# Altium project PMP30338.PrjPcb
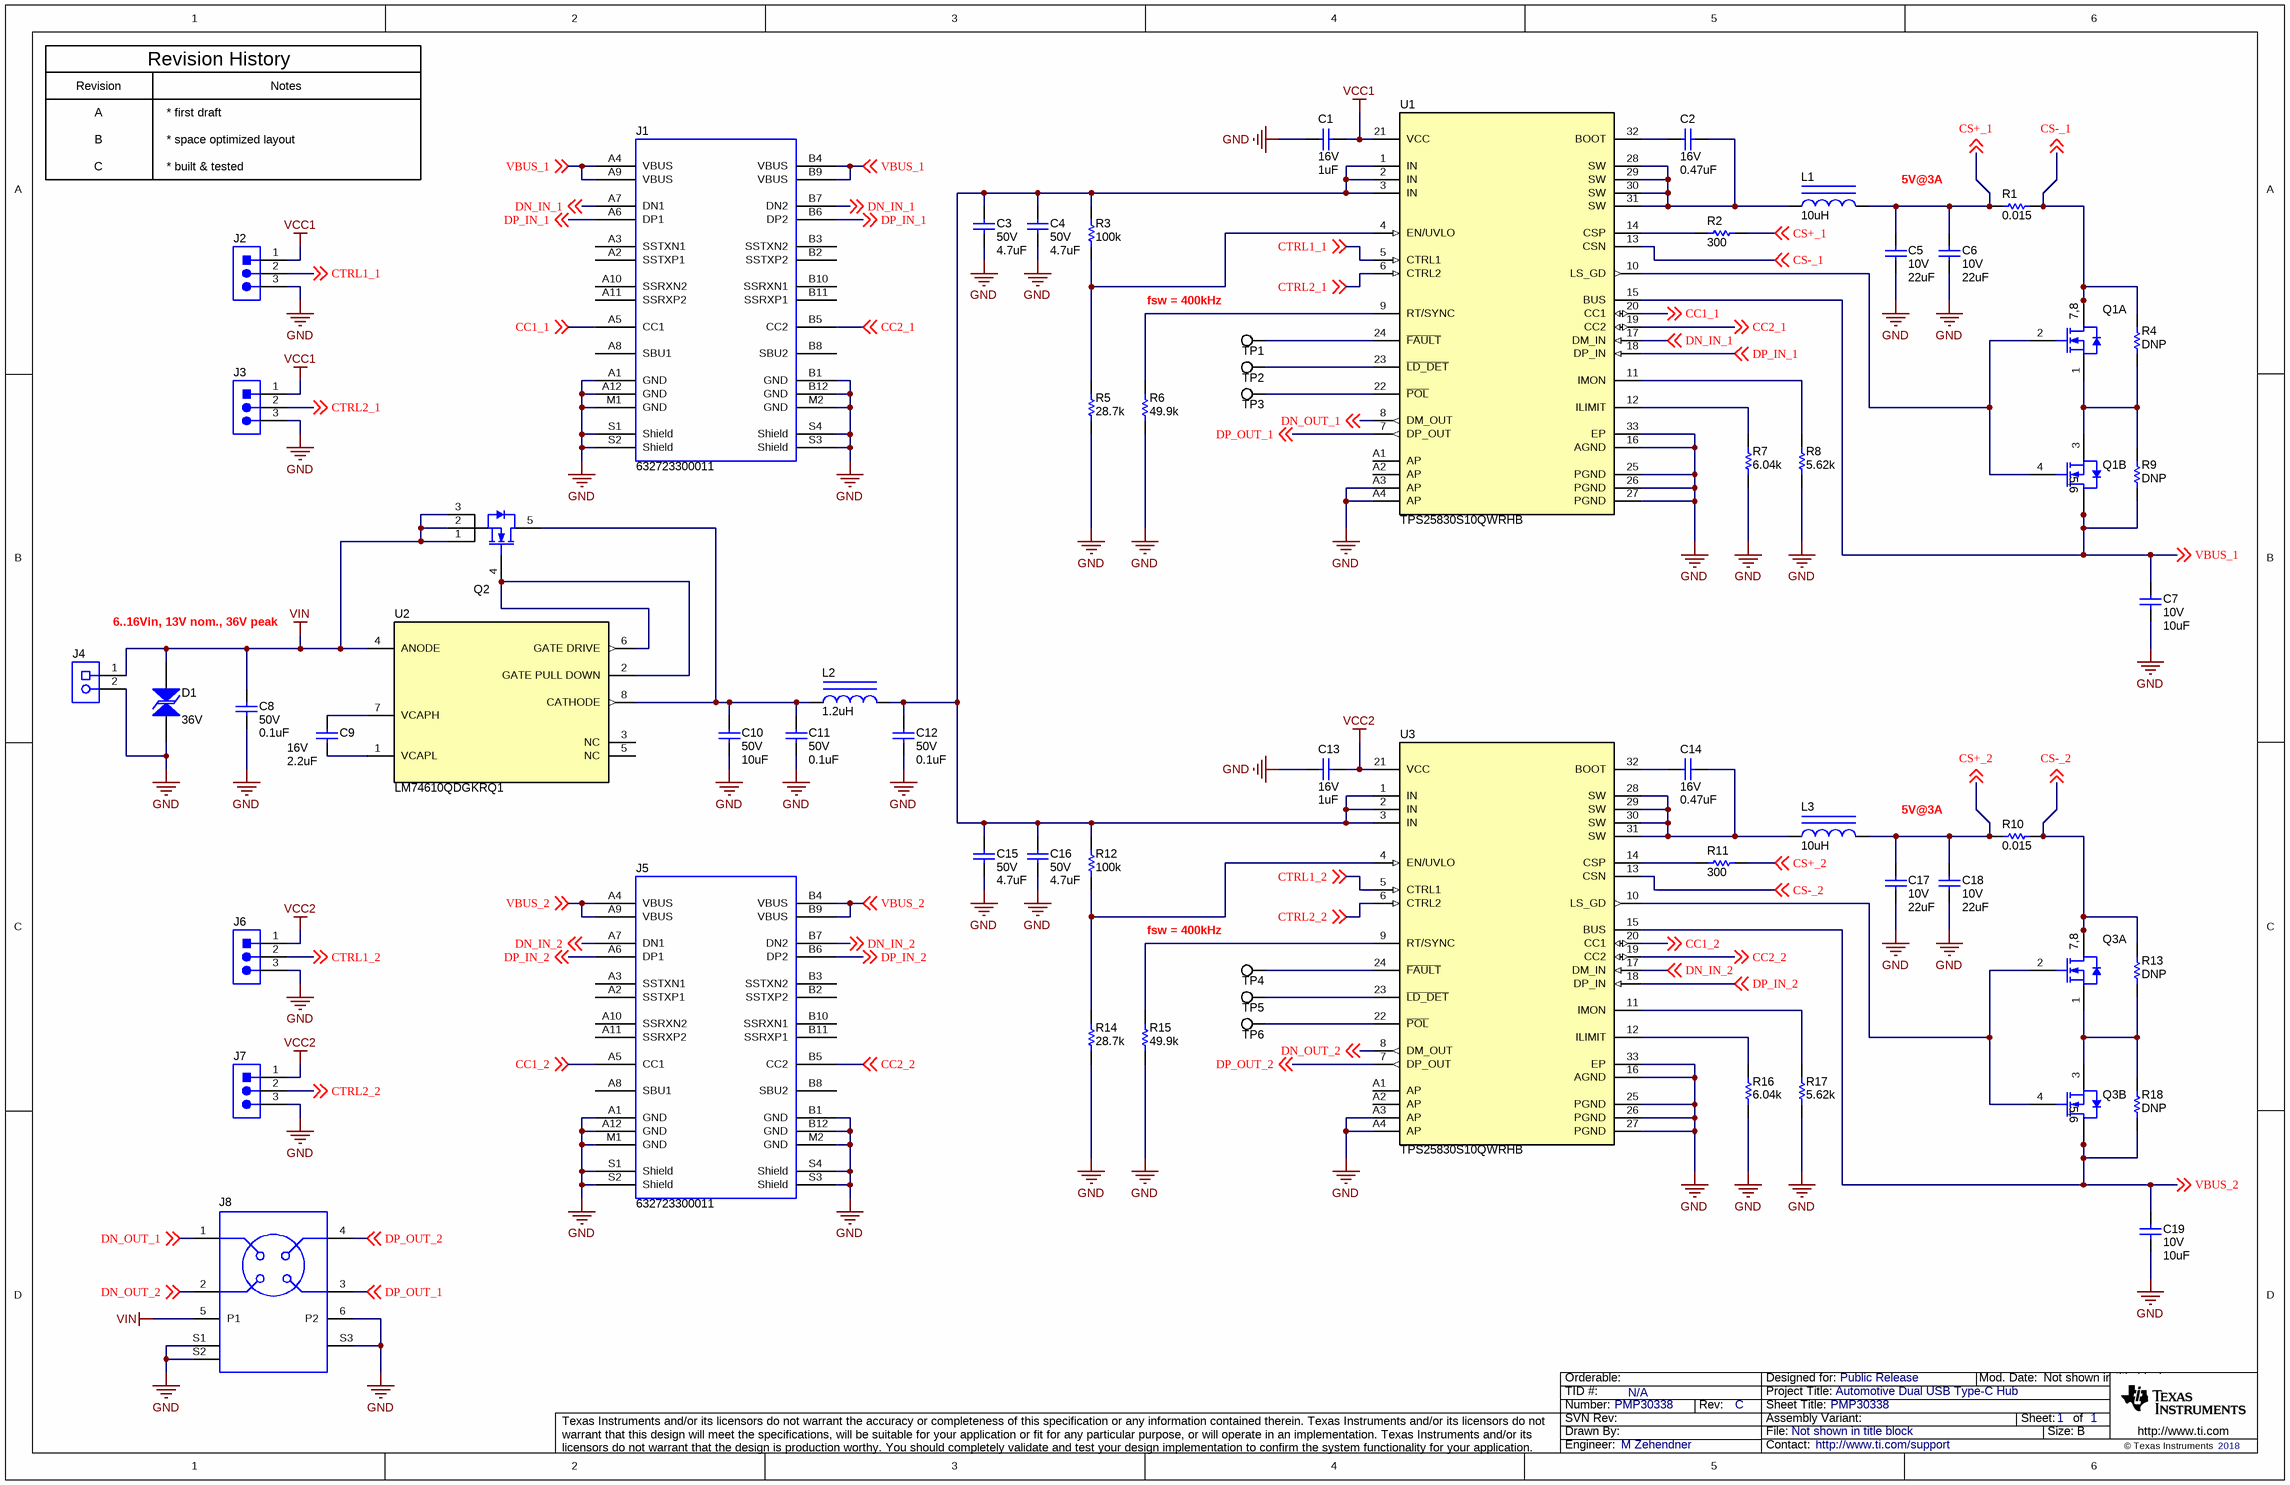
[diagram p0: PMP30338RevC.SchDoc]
TID: N/A; TechSupport: http://www.ti.com/support; SCH_Rev: C; PRJ_Title: Automotive Dual USB Type-C Hub; PRJ_Number: PMP30338; PRJ_Engineer: M Zehendner; PRJ_Customer: Public Release; PCB_Rev: B; PCB_Layout: Who did the Layout?; CopyrightYear: 2018
1 sheet, 61 parts. Net scope: global (net labels, ports and power ports of the same name join across sheets).
Board file: PMP30338.PcbDoc

## Sheet PMP30338RevC.SchDoc: PMP30338
size 431 x 279 mm; Date: Not shown in title block; ApprovedBy: Not shown in title block; CheckedBy: Not shown in title block; Author: Not shown in title block; CompanyName: Not shown in title block; Engineer: Not shown in title block; Organization: Not shown in title block; Address1: Not shown in title block; Address2: Not shown in title block; Address3: Not shown in title block; Address4: Not shown in title block; DocumentNumber: 1; Revision: Use project parameter SCH_Rev; SheetNumber: 1; SheetTotal: 1; PageSetup: Record=PageOptions¦CenterHorizontal=True¦CenterVertical=True¦PrintScale=1.00¦XCorrection=1.00¦YCorrection=1.00¦PrintKind=0¦BorderSize=5000000¦LeftOffset=0¦BottomOffset=0¦Orientation=2¦PaperLength=1000¦PaperWidth=1000¦Scale=100¦PaperSource=15¦PrintQuality=600¦MediaType=1¦DitherType=10¦PaperKind=Letter¦PrintScaleMode=1

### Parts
C1  VDC_V: 16V  ValueDisplayed: 1uF  [0805_HV]  (hidden comment: GRM21BR71C105MA01L)
C2  VDC_V: 16V  ValueDisplayed: 0.47uF  [0603]  (hidden comment: GRM188R71C474KA88D)
C3  VDC_V: 50V  ValueDisplayed: 4.7uF  [1206_180]  (hidden comment: GRM31CR71H475KA12L)
C4  VDC_V: 50V  ValueDisplayed: 4.7uF  [1206_180]  (hidden comment: GRM31CR71H475KA12L)
C5  VDC_V: 10V  ValueDisplayed: 22uF  [1210_270]  (hidden comment: GRM32ER71A226ME20L)
C6  VDC_V: 10V  ValueDisplayed: 22uF  [1210_270]  (hidden comment: GRM32ER71A226ME20L)
C7  VDC_V: 10V  ValueDisplayed: 10uF  [0805_HV]  (hidden comment: GRM21BR71A106ME51L)
C8  VDC_V: 50V  ValueDisplayed: 0.1uF  [0603]  (hidden comment: GRM188R71H104KA93D)
C9  VDC_V: 16V  ValueDisplayed: 2.2uF  [0805_HV]  (hidden comment: GRM219R71C225KE15)
C10  VDC_V: 50V  ValueDisplayed: 10uF  [1210_270]  (hidden comment: GRM32ER71H106MA12)
C11  VDC_V: 50V  ValueDisplayed: 0.1uF  [0603]  (hidden comment: GRM188R71H104KA93D)
C12  VDC_V: 50V  ValueDisplayed: 0.1uF  [0603]  (hidden comment: GRM188R71H104KA93D)
C13  VDC_V: 16V  ValueDisplayed: 1uF  [0805_HV]  (hidden comment: GRM21BR71C105MA01L)
C14  VDC_V: 16V  ValueDisplayed: 0.47uF  [0603]  (hidden comment: GRM188R71C474KA88D)
C15  VDC_V: 50V  ValueDisplayed: 4.7uF  [1206_180]  (hidden comment: GRM31CR71H475KA12L)
C16  VDC_V: 50V  ValueDisplayed: 4.7uF  [1206_180]  (hidden comment: GRM31CR71H475KA12L)
C17  VDC_V: 10V  ValueDisplayed: 22uF  [1210_270]  (hidden comment: GRM32ER71A226ME20L)
C18  VDC_V: 10V  ValueDisplayed: 22uF  [1210_270]  (hidden comment: GRM32ER71A226ME20L)
C19  VDC_V: 10V  ValueDisplayed: 10uF  [0805_HV]  (hidden comment: GRM21BR71A106ME51L)
D1  value 36V  [SMB-Bi]  (hidden comment: SM6T42CAY)
J1  632723300011  [Wurth_632_723_300_011]
J2  800-10-003-10-001000  [Mill-Max_800-10-003-10-001000]  (value not drawn)
J3  800-10-003-10-001000  [Mill-Max_800-10-003-10-001000]  (value not drawn)
J4  691 101 710 002  [Wurth_691101710002]  (value not drawn)
J5  632723300011  [Wurth_632_723_300_011]
J6  800-10-003-10-001000  [Mill-Max_800-10-003-10-001000]  (value not drawn)
J7  800-10-003-10-001000  [Mill-Max_800-10-003-10-001000]  (value not drawn)
J8  99S20D-40MA5-D  [Rosenberger_99S20D-40MA5-D]  (value not drawn)
L1  ValueDisplayed: 10uH  [XAL5050]  (hidden comment: XAL5050-103MEB)
L2  ValueDisplayed: 1.2uH  [XAL5030]  (hidden comment: XAL5030-122MEB)
L3  ValueDisplayed: 10uH  [XAL5050]  (hidden comment: XAL5050-103MEB)
Q1  BUK9K8R7-40E,115  [SOT1205]  (value not drawn)  (parts A,B of 2)
Q2  SQJ412EP-T1-GE3  [PowerPAK_SO-8L]  (value not drawn)
Q3  BUK9K8R7-40E,115  [SOT1205]  (value not drawn)  (parts A,B of 2)
R1  ValueDisplayed: 0.015  [1206]  (hidden comment: CSR1206FK15L0)
R2  ValueDisplayed: 300  [0603]  (hidden comment: CRCW0603300RJNEA)
R3  ValueDisplayed: 100k  [0603]  (hidden comment: CRCW0603100KFKEA)
R4  ValueDisplayed: DNP  [1206]  (hidden comment: RC1206JR-070RL)
R5  ValueDisplayed: 28.7k  [0603]  (hidden comment: CRCW060328K7FKEA)
R6  ValueDisplayed: 49.9k  [0603]  (hidden comment: CRCW060349K9FKEA)
R7  ValueDisplayed: 6.04k  [0603]  (hidden comment: CRCW06036K04FKEA)
R8  ValueDisplayed: 5.62k  [0603]  (hidden comment: CRCW06035K62FKEA)
R9  ValueDisplayed: DNP  [1206]  (hidden comment: RC1206JR-070RL)
R10  ValueDisplayed: 0.015  [1206]  (hidden comment: CSR1206FK15L0)
R11  ValueDisplayed: 300  [0603]  (hidden comment: CRCW0603300RJNEA)
R12  ValueDisplayed: 100k  [0603]  (hidden comment: CRCW0603100KFKEA)
R13  ValueDisplayed: DNP  [1206]  (hidden comment: RC1206JR-070RL)
R14  ValueDisplayed: 28.7k  [0603]  (hidden comment: CRCW060328K7FKEA)
R15  ValueDisplayed: 49.9k  [0603]  (hidden comment: CRCW060349K9FKEA)
R16  ValueDisplayed: 6.04k  [0603]  (hidden comment: CRCW06036K04FKEA)
R17  ValueDisplayed: 5.62k  [0603]  (hidden comment: CRCW06035K62FKEA)
R18  ValueDisplayed: DNP  [1206]  (hidden comment: RC1206JR-070RL)
TP1  5012  [Keystone5012]  (value not drawn)
TP2  5012  [Keystone5012]  (value not drawn)
TP3  5012  [Keystone5012]  (value not drawn)
TP4  5012  [Keystone5012]  (value not drawn)
TP5  5012  [Keystone5012]  (value not drawn)
TP6  5012  [Keystone5012]  (value not drawn)
U1  TPS25830S10QWRHB  [RHB0032R]
U2  LM74610QDGKRQ1  [DGK0008A_L]
U3  TPS25830S10QWRHB  [RHB0032R]

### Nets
GND: C1.2 C3.2 C4.2 C5.2 C6.2 C7.2 C8.2 C10.2 C11.2 C12.2 C13.2 C15.2 C16.2 C17.2 C18.2 C19.2 D1.1 J1.A1(GND) J1.A12(GND) J1.B1(GND) J1.B12(GND) J1.M1(GND) J1.M2(GND) J1.S1(Shield) J1.S2(Shield) J1.S3(Shield) J1.S4(Shield) J2.3 J3.3 J4.2 J5.A1(GND) J5.A12(GND) J5.B1(GND) J5.B12(GND) J5.M1(GND) J5.M2(GND) J5.S1(Shield) J5.S2(Shield) J5.S3(Shield) J5.S4(Shield) J6.3 J7.3 J8.6(P2) J8.S1 J8.S2 J8.S3 R5.1 R6.1 R7.1 R8.1 R14.1 R15.1 R16.1 R17.1 U1.16(AGND) U1.25(PGND) U1.26(PGND) U1.27(PGND) U1.33(EP) U1.A3(AP) U1.A4(AP) U3.16(AGND) U3.25(PGND) U3.26(PGND) U3.27(PGND) U3.33(EP) U3.A3(AP) U3.A4(AP)
VCC1: C1.1 J2.1 J3.1 U1.21(VCC)
VCC2: C13.1 J6.1 J7.1 U3.21(VCC)
VIN: C8.1 D1.2 J4.1 J8.5(P1) Q2.1(S) Q2.2(S) Q2.3(S) U2.4(ANODE)
CC1_1: J1.A5(CC1) U1.20(CC1) ; off-sheet CC1_1
CC1_2: J5.A5(CC1) U3.20(CC1) ; off-sheet CC1_2
CC2_1: J1.B5(CC2) U1.19(CC2) ; off-sheet CC2_1
CC2_2: J5.B5(CC2) U3.19(CC2) ; off-sheet CC2_2
CS+_1: C5.1 C6.1 L1.2 R1.1 R2.2 ; off-sheet CS+_1
CS+_2: C17.1 C18.1 L3.2 R10.1 R11.2 ; off-sheet CS+_2
CS-_1: Q1.7(D) Q1.8(D) R1.2 R4.2 U1.13(CSN) ; off-sheet CS-_1
CS-_2: Q3.7(D) Q3.8(D) R10.2 R13.2 U3.13(CSN) ; off-sheet CS-_2
CTRL1_1: J2.2 U1.5(CTRL1) ; off-sheet CTRL1_1
CTRL1_2: J6.2 U3.5(CTRL1) ; off-sheet CTRL1_2
CTRL2_1: J3.2 U1.6(CTRL2) ; off-sheet CTRL2_1
CTRL2_2: J7.2 U3.6(CTRL2) ; off-sheet CTRL2_2
DN_IN_1: J1.A7(DN1) J1.B7(DN2) U1.17(DM_IN) ; off-sheet DN_IN_1
DN_IN_2: J5.A7(DN1) J5.B7(DN2) U3.17(DM_IN) ; off-sheet DN_IN_2
DN_OUT_1: J8.1 U1.8(DM_OUT) ; off-sheet DN_OUT_1
DN_OUT_2: J8.2 U3.8(DM_OUT) ; off-sheet DN_OUT_2
DP_IN_1: J1.A6(DP1) J1.B6(DP2) U1.18(DP_IN) ; off-sheet DP_IN_1
DP_IN_2: J5.A6(DP1) J5.B6(DP2) U3.18(DP_IN) ; off-sheet DP_IN_2
DP_OUT_1: J8.3 U1.7(DP_OUT) ; off-sheet DP_OUT_1
DP_OUT_2: J8.4 U3.7(DP_OUT) ; off-sheet DP_OUT_2
VBUS_1: C7.1 J1.A4(VBUS) J1.A9(VBUS) J1.B4(VBUS) J1.B9(VBUS) Q1.5(D) Q1.6(D) R9.1 U1.15(BUS) ; off-sheet VBUS_1
VBUS_2: C19.1 J5.A4(VBUS) J5.A9(VBUS) J5.B4(VBUS) J5.B9(VBUS) Q3.5(D) Q3.6(D) R18.1 U3.15(BUS) ; off-sheet VBUS_2
NetC2_1: C2.1 L1.1 U1.28(SW) U1.29(SW) U1.30(SW) U1.31(SW)
NetC2_2: C2.2 U1.32(BOOT)
NetC3_1: C3.1 C4.1 C12.1 C15.1 C16.1 L2.2 R3.2 R12.2 U1.1(IN) U1.2(IN) U1.3(IN) U3.1(IN) U3.2(IN) U3.3(IN)
NetC9_1: C9.1 U2.7(VCAPH)
NetC9_2: C9.2 U2.1(VCAPL)
NetC10_1: C10.1 C11.1 L2.1 Q2.5(D) U2.8(CATHODE)
NetC14_1: C14.1 L3.1 U3.28(SW) U3.29(SW) U3.30(SW) U3.31(SW)
NetC14_2: C14.2 U3.32(BOOT)
NetQ1_1: Q1.1(S) Q1.3(S) R4.1 R9.2
NetQ1_2: Q1.2(G) Q1.4(G) U1.10(LS_GD)
NetQ2_4: Q2.4(G) U2.2(GATE_PULL_DOWN) U2.6(GATE_DRIVE)
NetQ3_1: Q3.1(S) Q3.3(S) R13.1 R18.2
NetQ3_2: Q3.2(G) Q3.4(G) U3.10(LS_GD)
NetR2_1: R2.1 U1.14(CSP)
NetR3_1: R3.1 R5.2 U1.4(EN/UVLO)
NetR6_2: R6.2 U1.9(RT/SYNC)
NetR7_2: R7.2 U1.12(ILIMIT)
NetR8_2: R8.2 U1.11(IMON)
NetR11_1: R11.1 U3.14(CSP)
NetR12_1: R12.1 R14.2 U3.4(EN/UVLO)
NetR15_2: R15.2 U3.9(RT/SYNC)
NetR16_2: R16.2 U3.12(ILIMIT)
NetR17_2: R17.2 U3.11(IMON)
NetTP1_1: TP1.1 U1.24(~{FAULT})
NetTP2_1: TP2.1 U1.23(~{LD_DET})
NetTP3_1: TP3.1 U1.22(~{POL})
NetTP4_1: TP4.1 U3.24(~{FAULT})
NetTP5_1: TP5.1 U3.23(~{LD_DET})
NetTP6_1: TP6.1 U3.22(~{POL})

Not connected (* = marked no-connect by the designer): J1 A2(SSTXP1) A3(SSTXN1) A8(SBU1) A10(SSRXN2) A11(SSRXP2) B2(SSTXP2) B3(SSTXN2) B8(SBU2) B10(SSRXN1) B11(SSRXP1); J5 A2(SSTXP1) A3(SSTXN1) A8(SBU1) A10(SSRXN2) A11(SSRXP2) B2(SSTXP2) B3(SSTXN2) B8(SBU2) B10(SSRXN1) B11(SSRXP1); U1 A1(AP) A2(AP); U2 3(NC) 5(NC); U3 A1(AP) A2(AP)

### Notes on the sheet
- Revision
- Revision History
- Notes
- A
- B
- C
- * first draft
- * space optimized layout
- * built & tested
- 5V@3A
- fsw = 400kHz
- 6..16Vin, 13V nom., 36V peak

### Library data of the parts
C1 C13 = CMP-0008324-2: CAP, CERM, 1 uF, 16 V, +/- 20%, X7R, 0805; Manufacturer: MuRata; TaMin_C: -55°C; ESR_ohm: 3m; Polarized: N; SizeAreaWB_mm2: 6.75; Value1: 0.003 ohm; U/M: EA; Value: 1uF; TaMax_C: 125°C; SizeZ_mm: 1.45; SizeX_mm: 2; SizeY_mm: 1.25; Cap_Case: 0805; SizeArea_mm2: 2.5; Cap_F: 1µF; AEC Category: Q200
C2 C14 = CMP-0007398-2: CAP, CERM, 0.47 uF, 16 V, +/- 10%, X7R, 0603; Manufacturer: MuRata; TaMin_C: -55°C; Polarized: N; SizeAreaWB_mm2: 4.68; Value1: Unknown; U/M: EA; Value: 0.47uF; TaMax_C: 125°C; SizeZ_mm: 1; SizeX_mm: 1.6; SizeY_mm: 0.8; SizeArea_mm2: 1.28; Cap_F: 470nF; AEC Category: Q200
C3 C4 C15 C16 = CMP-0008969-2: CAP, CERM, 4.7 uF, 50 V, +/- 10%, X7R, 1206; Manufacturer: MuRata; TaMin_C: -55°C; Polarized: N; SizeAreaWB_mm2: 10.92; Value1: Unknown; U/M: EA; Value: 4.7uF; TaMax_C: 125°C; SizeZ_mm: 1.8; SizeX_mm: 3.2; SizeY_mm: 1.6; Cap_Case: 2220; SizeArea_mm2: 5.12; Cap_F: 4.7µF; AEC Category: Q200
C5 C6 C17 C18 = CMP-0009219-2: CAP, CERM, 22 uF, 10 V, +/- 10%, X7R, 1210; Manufacturer: MuRata; TaMin_C: -55°C; ESR_ohm: 2m; Polarized: N; SizeAreaWB_mm2: 14.7; Value1: 0.002 ohm; U/M: EA; Value: 22uF; TaMax_C: 125°C; SizeZ_mm: 2.7; SizeX_mm: 3.2; SizeY_mm: 2.5; Cap_Case: 1210; SizeArea_mm2: 8; Cap_F: 22µF; IRMS_A: 3.2A; AEC Category: Q200
C7 C19 = CMP-0008316-2: CAP, CERM, 10 uF, 10 V, +/- 20%, X7R, 0805; Manufacturer: MuRata; TaMin_C: -55°C; Polarized: N; SizeAreaWB_mm2: 6.75; Value1: Unknown; U/M: EA; Value: 10uF; TaMax_C: 125°C; SizeZ_mm: 1.45; SizeX_mm: 2; SizeY_mm: 1.25; Cap_Case: 0805; SizeArea_mm2: 2.5; Cap_F: 10µF; AEC Category: Q200
C8 C11 C12 = CMP-0007434-2: CAP, CERM, 0.1 uF, 50 V, +/- 10%, X7R, 0603; Manufacturer: MuRata; TaMin_C: -55°C; Polarized: N; SizeAreaWB_mm2: 4.68; Value1: Unknown; U/M: EA; Value: 0.1uF; TaMax_C: 125°C; SizeZ_mm: 1; SizeX_mm: 1.6; SizeY_mm: 0.8; SizeArea_mm2: 1.28; Cap_F: 100nF; AEC Category: Q200
C9 = CMP-0008211-2: CAP, CERM, 2.2 uF, 16 V, +/- 10%, X7R, 0805; Manufacturer: MuRata; TaMin_C: -55°C; Polarized: N; SizeAreaWB_mm2: 6.75; Value1: Unknown; U/M: EA; Value: 2.2uF; TaMax_C: 125°C; SizeZ_mm: 1.45; SizeX_mm: 2; SizeY_mm: 1.25; Cap_Case: 0805; SizeArea_mm2: 2.5; Cap_F: 2.2µF; AEC Category: Q200
C10 = CMP-0009227-2: CAP, CERM, 10 uF, 50 V, +/- 20%, X7R, 1210; Manufacturer: MuRata; TaMin_C: -55°C; Polarized: N; SizeAreaWB_mm2: 14.7; Value1: Unknown; U/M: EA; Value: 10uF; TaMax_C: 125°C; SizeZ_mm: 2.7; SizeX_mm: 3.2; SizeY_mm: 2.5; Cap_Case: 1210; SizeArea_mm2: 8; Cap_F: 10µF; AEC Category: Q200
D1 = CMP-0006049-2: Diode, TVS, Bi, 36 V, 76 Vc, AEC-Q101, SMB; Manufacturer: STMicroelectronics; Value1: W; U/M: EA; AEC Qualified: Y; AEC Category: Q101
J1 J5 = CMP-0080891-1: Connector, Receptacle, USB Type C, R/A; Manufacturer: Wurth Elektronik; Current_A: 3A; Gender: Female; Voltage_V: 5V; ContactFinish: Gold; Cert_UL: Y
J2 J3 J6 J7 = CMP-0055086-1: Header, 100mil, 3x1, TH; Manufacturer: Mill-Max; CNHeader: TRUE; Green_Lifecycle: Active; Green_REACh: Passed; CT: FALSE
J4 = CMP-0054828-1: Terminal Block, 5 mm, 2x1, Tin, TH; Manufacturer: Wurth Elektronik; CNHeader: FALSE; Green_Lifecycle: Active; Green_REACh: Passed; CT: TRUE
J8 = CMP-0055816-1: RF Coaxial Connector, Bordeaux, R/A, TH; Manufacturer: Rosenberger; CNHeader: FALSE; Shrouded: Y; Gender: Male; Voltage_V: 100V; CompType: Plug; ContactFinish: Gold
L1 L3 = CMP-0061007-1: Inductor, Shielded, Composite, 10 uH, 4.9 A, 0.05 ohm, SMD; Manufacturer: Coilcraft; Isat: 4.9A @ 30% inductance drop; Irms: 4.9A @ 40C rise; Green_Lifecycle: Not Set; SizeAreaWB_mm2: 54.4544; DCR_ohm: 0.05; Green_REACh: Incomplete; Value: 10uH; Imax_A: 4.9A; SizeZ_mm: 5.1; SizeX_mm: 5.28; SizeY_mm: 5.48; SizeArea_mm2: 28.9344; Ind_H: 10µH; AEC Category: Q200
L2 = CMP-0060999-1: Inductor, Shielded, Composite, 1.2 uH, 11.1 A, 0.01 ohm, SMD; Manufacturer: Coilcraft; Isat: 12.5A @ 30% inductance drop; Irms: 11.1A @ 40C rise; Green_Lifecycle: Not Set; SizeAreaWB_mm2: 54.4544; DCR_ohm: 0.01; Green_REACh: Incomplete; Value: 1.2uH; Imax_A: 11.1A; SizeZ_mm: 3.1; SizeX_mm: 5.28; SizeY_mm: 5.48; SizeArea_mm2: 28.9344; Ind_H: 1.2µH; AEC Category: Q200
Q1 Q3 = CMP-0000698-2: MOSFET, 2-CH, N-CH, 40 V, 30 A, AEC-Q101, SOT1205; Alternate Manufacturer: None; Manufacturer: Nexperia; SizeZ_mm: 1.05; ChType: N; Value2: 14.5 nC; VdsMax_V: 40V; SizeX_mm: 6.05; SizeY_mm: 5.125; Vgs_V: 10V; AEC Qualified: Y; Value: 40V; SizeArea_mm2: 31.00625; AEC Category: Q101; IdsMax_A: 30A; SizeAreaWB_mm2: 57.35625; QgTyp_nC: 14.5
Q2 = CMP-0000746-1: MOSFET, N-CH, 40 V, 32 A, PowerPAK_SO-8L; Alternate Manufacturer: None; Manufacturer: Vishay-Siliconix; SizeZ_mm: 1.14; ChType: N; Value2: 80 nC; Value1: 0.005; VdsMax_V: 40V; SizeX_mm: 6.15; SizeY_mm: 5.13; Vgs_V: 20V; Value: 40V; Rdson45_ohm: 5.2m; SizeArea_mm2: 31.5495; AEC Category: Q101; IdsMax_A: 32A; SizeAreaWB_mm2: 58.1095; U/M: EA; QgTyp_nC: 80
R1 R10 = CMP-0017258-2: RES, 0.015, 1%, 0.5 W, 1206; Manufacturer: Stackpole Electronics Inc; Power_W: 500mW; TempCo: 100 ppm/C; Value_Code: R015; U/M: EA; Value: 0.015; EIA_Code: E96; SizeX_mm: 3.2; SizeY_mm: 1.6; SizeZ_mm: 1.35; Value2: 0.5W; SizeArea_mm2: 5.12; AEC Category: Q200
R2 R11 = CMP-0025781-2: RES, 300, 5%, 0.1 W, 0603; Manufacturer: Vishay-Dale; Power_W: 100mW; TempCo: 200 ppm/C; Value_Code: 300R; U/M: EA; Value: 300; EIA_Code: E24; SizeX_mm: 1.6; SizeY_mm: 0.8; SizeZ_mm: 1; Value2: 0.1W; SizeArea_mm2: 1.28; VDC_V: 75V; AEC Category: Q200
R3 R12 = CMP-0021990-2: RES, 100 k, 1%, 0.1 W, 0603; Manufacturer: Vishay-Dale; Power_W: 100mW; TempCo: 100 ppm/C; U/M: EA; Value: 100k; EIA_Code: E96; SizeX_mm: 1.6; SizeY_mm: 0.8; SizeZ_mm: 1; Value2: 0.1W; SizeArea_mm2: 1.28; VDC_V: 75V; AEC Category: Q200
R4 R9 R13 R18 = CMP-0018759-2: RES, 0, 5%, 0.25 W, 1206; Manufacturer: Yageo America; Power_W: 250mW; TempCo: 200 ppm/C; Value_Code: 0000; U/M: EA; Value: 0; EIA_Code: E24; SizeX_mm: 3.2; SizeY_mm: 1.6; SizeZ_mm: 1.35; Value2: 0.25W; SizeArea_mm2: 5.12; VDC_V: 200V; AEC Category: Q200
R5 R14 = CMP-0022261-4: RES, 28.7 k, 1%, 0.1 W, AEC-Q200 Grade 0, 0603; Manufacturer: Vishay-Dale; Power_W: 100mW; TempCo: 100 ppm/C; Value_Code: 28k7; Value: 28.7k; EIA_Code: E96; SizeX_mm: 1.6; SizeY_mm: 0.8; SizeZ_mm: 1; Value2: 0.1W; SizeArea_mm2: 1.28; AEC Qualified: Y; VDC_V: 75V; AEC Category: Q200; AEC Grade: 0
R6 R15 = CMP-0022447-4: RES, 49.9 k, 1%, 0.1 W, AEC-Q200 Grade 0, 0603; Manufacturer: Vishay-Dale; Power_W: 100mW; TempCo: 100 ppm/C; Value_Code: 49k9; Value: 49.9k; EIA_Code: E96; SizeX_mm: 1.6; SizeY_mm: 0.8; SizeZ_mm: 1; Value2: 0.1W; SizeArea_mm2: 1.28; AEC Qualified: Y; VDC_V: 75V; AEC Category: Q200; AEC Grade: 0
R7 R16 = CMP-0022558-4: RES, 6.04 k, 1%, 0.1 W, AEC-Q200 Grade 0, 0603; Manufacturer: Vishay-Dale; Power_W: 100mW; TempCo: 100 ppm/C; Value_Code: 6k04; Value: 6.04k; EIA_Code: E96; SizeX_mm: 1.6; SizeY_mm: 0.8; SizeZ_mm: 1; Value2: 0.1W; SizeArea_mm2: 1.28; AEC Qualified: Y; VDC_V: 75V; AEC Category: Q200; AEC Grade: 0
R8 R17 = CMP-0022513-4: RES, 5.62 k, 1%, 0.1 W, AEC-Q200 Grade 0, 0603; Manufacturer: Vishay-Dale; Power_W: 100mW; TempCo: 100 ppm/C; Value_Code: 5k62; Value: 5.62k; EIA_Code: E96; SizeX_mm: 1.6; SizeY_mm: 0.8; SizeZ_mm: 1; Value2: 0.1W; SizeArea_mm2: 1.28; AEC Qualified: Y; VDC_V: 75V; AEC Category: Q200; AEC Grade: 0
TP1-TP6 = CMP-0055149-1: Test Point, Multipurpose, White, TH; Manufacturer: Keystone; CNHeader: FALSE; Green_Lifecycle: Active; Green_REACh: Passed; ContactFinish: Silver; CT: TRUE
U1 U3 = CMP-0074898-3: USB Type-C and BC1.2 5V 3.5A Output, 36V Input Synchronous Buck with Cable Compensation, RHB0032R (VQFN-32); Manufacturer: Texas Instruments; SizeX_mm: 5.0; CompType: IC; SizeZ_mm: 1.0; SizeArea_mm2: 25.0; SizeAreaWB_mm2: 49.0; U/M: EA
U2 = CMP-0076397-1: Zero Iq Reverse Polarity Protection Smart Diode Controller, DGK0008A (VSSOP-8); Manufacturer: Texas Instruments; SizeAreaWB_mm2: 35.955; SizeArea_mm2: 15.655; SizeZ_mm: 1.1; Green_REACh: Passed; SizeY_mm: 3.1; Green_Lifecycle: Active; U/M: EA; CompType: IC; SizeX_mm: 5.05

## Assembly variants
001: not fitted FID1 FID2 FID3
